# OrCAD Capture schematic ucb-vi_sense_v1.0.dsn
size C; title: UCB_VI_Sense; rev: 1.0; company: University of Arkansas (NCREPT); note: 700 W. Research Center Blvd.; note: Fayetteville, AR 72701
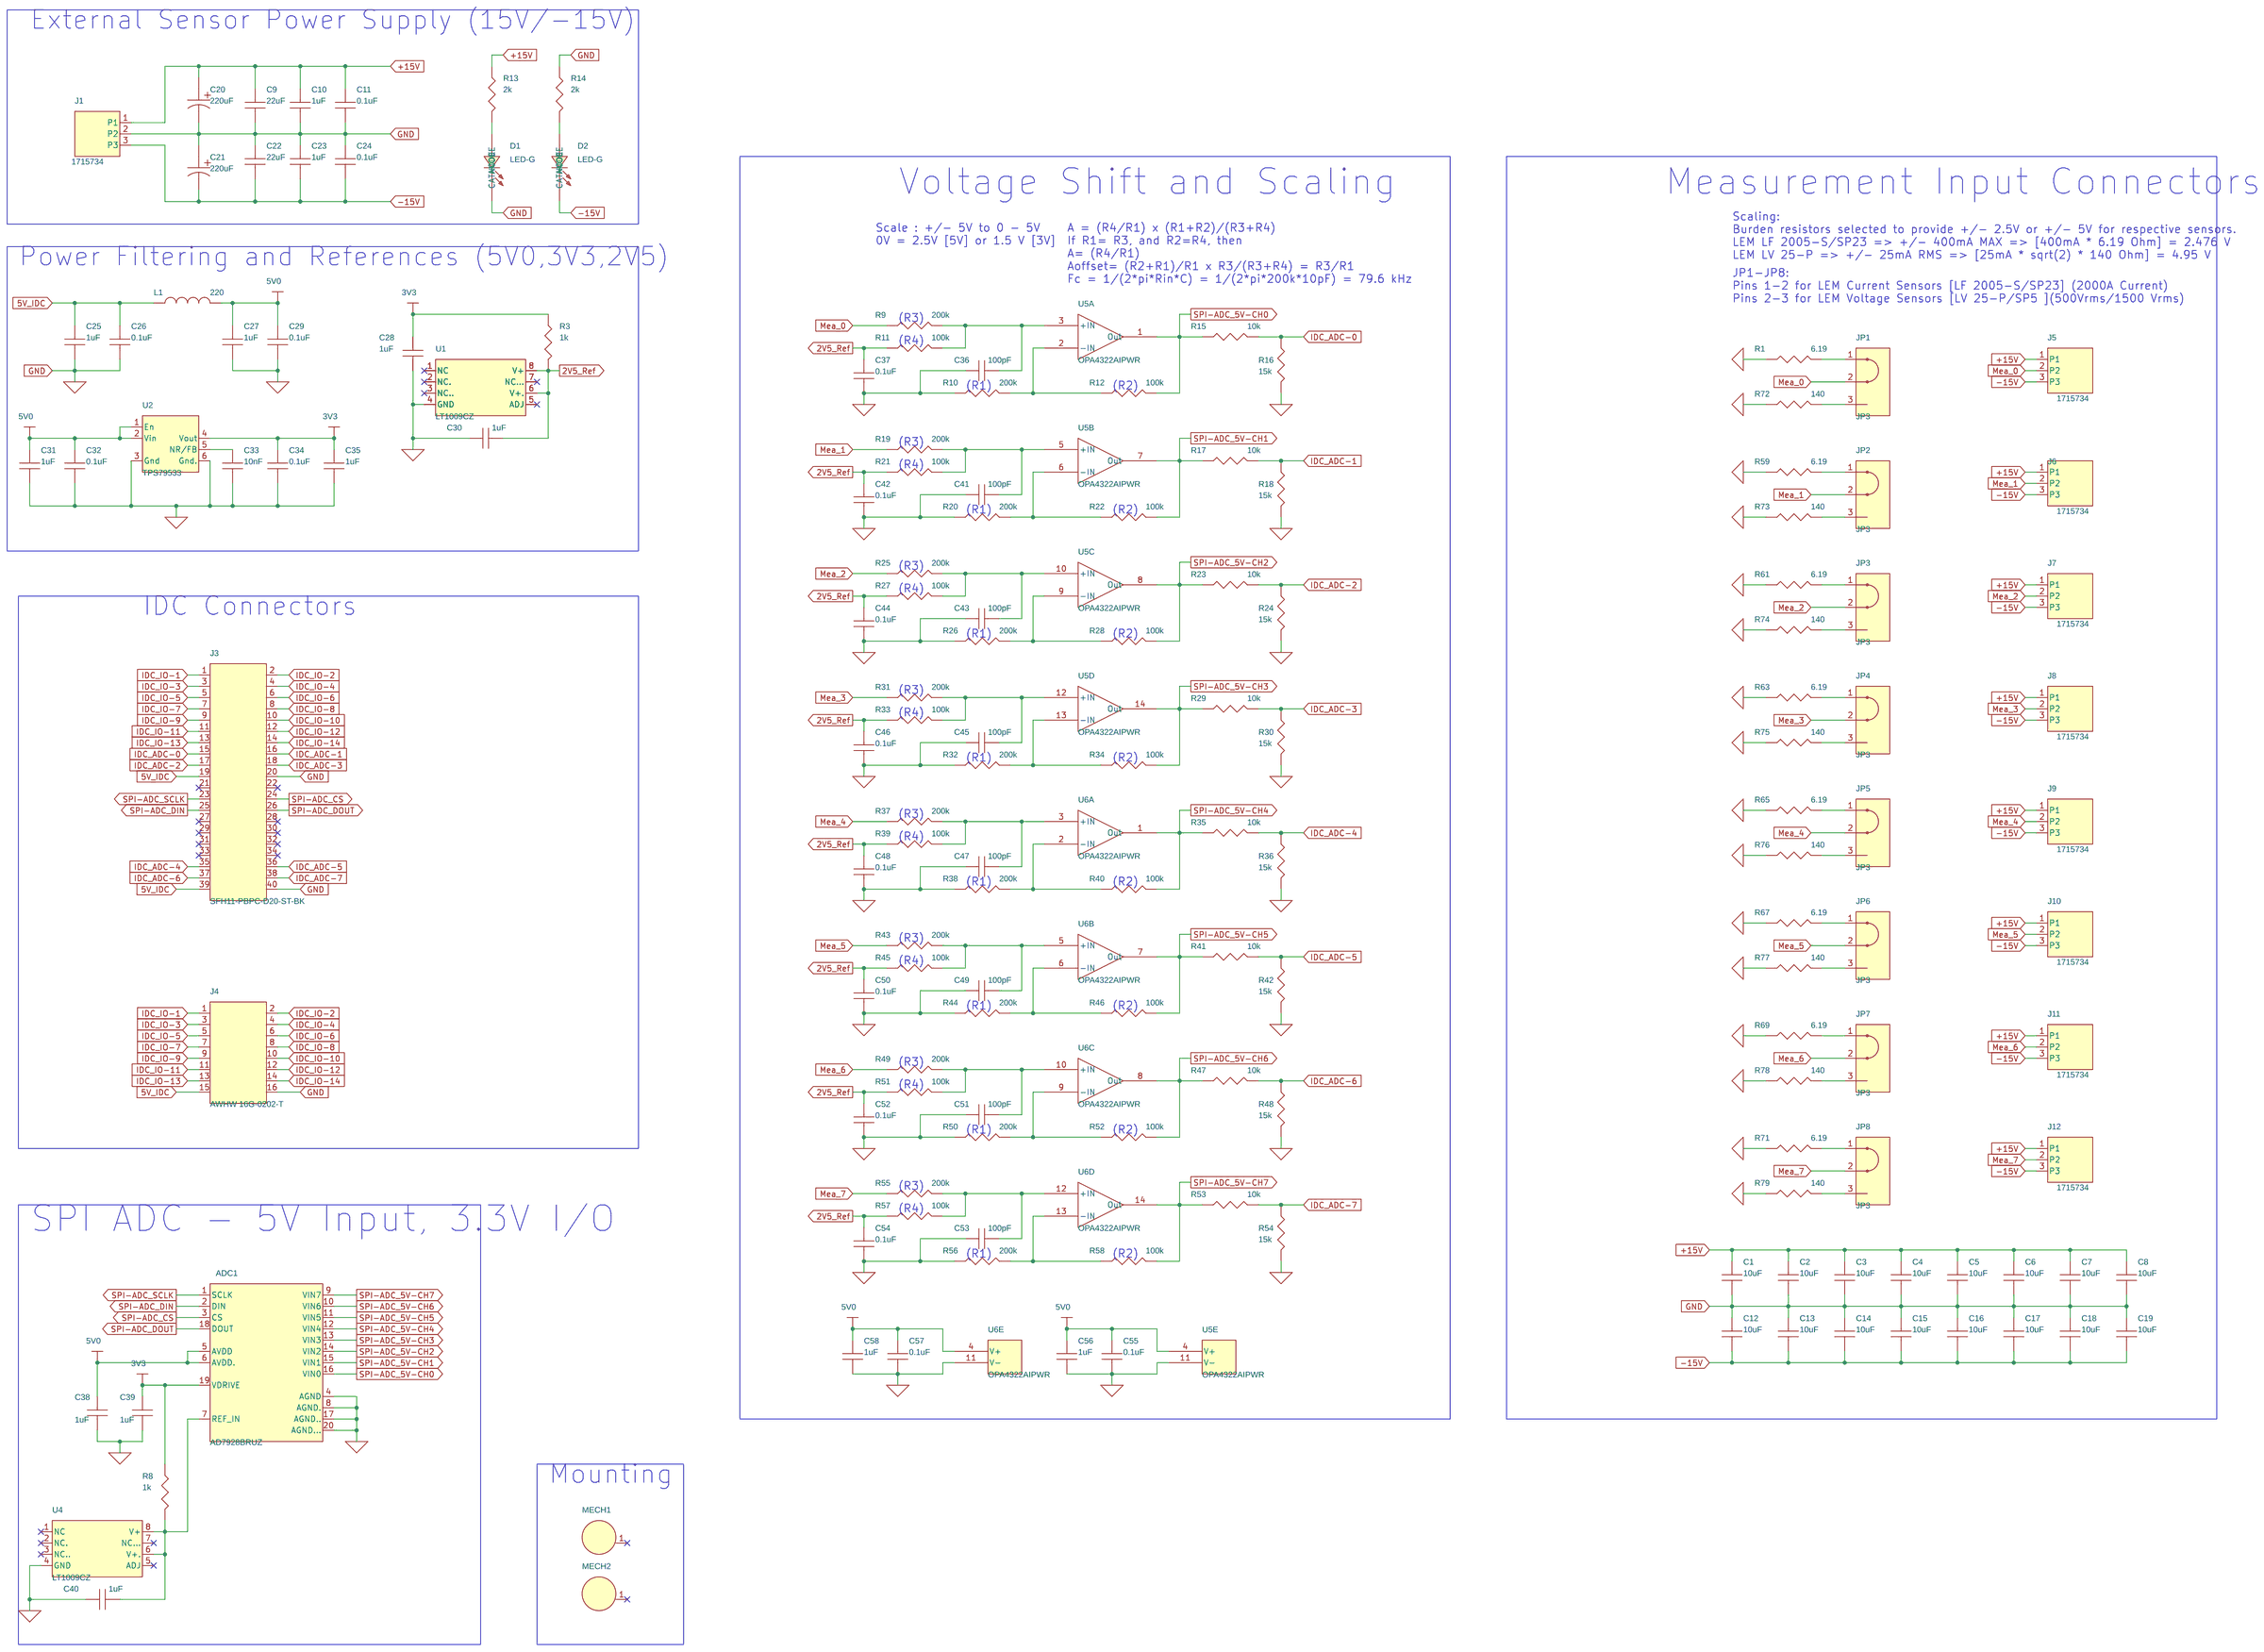
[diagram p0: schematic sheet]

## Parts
ADC1  AD7928BRUZ  [20-TSSOP]
C1  10uF  [C_1206]
C2  10uF  [C_1206]
C3  10uF  [C_1206]
C4  10uF  [C_1206]
C5  10uF  [C_1206]
C6  10uF  [C_1206]
C7  10uF  [C_1206]
C8  10uF  [C_1206]
C9  22uF  [C_0805]
C10  1uF  [C_0603]
C11  0.1uF  [C_0603]
C12  10uF  [C_1206]
C13  10uF  [C_1206]
C14  10uF  [C_1206]
C15  10uF  [C_1206]
C16  10uF  [C_1206]
C17  10uF  [C_1206]
C18  10uF  [C_1206]
C19  10uF  [C_1206]
C20  220uF  [EEE-FK-F]
C21  220uF  [EEE-FK-F]
C22  22uF  [C_0805]
C23  1uF  [C_0603]
C24  0.1uF  [C_0603]
C25  1uF  [C_0603]
C26  0.1uF  [C_0603]
C27  1uF  [C_0603]
C28  1uF  [C_0603]
C29  0.1uF  [C_0603]
C30  1uF  [C_0603]
C31  1uF  [C_0603]
C32  0.1uF  [C_0603]
C33  10nF  [C_0603]
C34  0.1uF  [C_0603]
C35  1uF  [C_0603]
C36  100pF  [C_0603]
C37  0.1uF  [C_0603]
C38  1uF  [C_0603]
C39  1uF  [C_0603]
C40  1uF  [C_0603]
C41  100pF  [C_0603]
C42  0.1uF  [C_0603]
C43  100pF  [C_0603]
C44  0.1uF  [C_0603]
C45  100pF  [C_0603]
C46  0.1uF  [C_0603]
C47  100pF  [C_0603]
C48  0.1uF  [C_0603]
C49  100pF  [C_0603]
C50  0.1uF  [C_0603]
C51  100pF  [C_0603]
C52  0.1uF  [C_0603]
C53  100pF  [C_0603]
C54  0.1uF  [C_0603]
C55  0.1uF  [C_0603]
C56  1uF  [C_0603]
C57  0.1uF  [C_0603]
C58  1uF  [C_0603]
D1  LED-G  [LED_0805-GREEN]
D2  LED-G  [LED_0805-GREEN]
J1  1715734  [1715734]
J3  SFH11-PBPC-D20-ST-BK  [40-IDC-F_MNT]
J4  AWHW 16G-0202-T  [16-IDC-M]
J5  1715734  [1715734]
J6  1715734  [1715734]
J7  1715734  [1715734]
J8  1715734  [1715734]
J9  1715734  [1715734]
J10  1715734  [1715734]
J11  1715734  [1715734]
J12  1715734  [1715734]
JP1  JP3  [J_1X3]
JP2  JP3  [J_1X3]
JP3  JP3  [J_1X3]
JP4  JP3  [J_1X3]
JP5  JP3  [J_1X3]
JP6  JP3  [J_1X3]
JP7  JP3  [J_1X3]
JP8  JP3  [J_1X3]
L1  220  [L_0805]
MECH1  Mech_Hole  [4-40_SCREW]
MECH2  Mech_Hole  [4-40_SCREW]
R1  6.19  [R_2512]
R3  1k  [R_0805]
R8  1k  [R_0805]
R9  200k  [R_0603]
R10  200k  [R_0603]
R11  100k  [R_0603]
R12  100k  [R_0603]
R13  2k  [R_0603]
R14  2k  [R_0603]
R15  10k  [R_0603]
R16  15k  [R_0603]
R17  10k  [R_0603]
R18  15k  [R_0603]
R19  200k  [R_0603]
R20  200k  [R_0603]
R21  100k  [R_0603]
R22  100k  [R_0603]
R23  10k  [R_0603]
R24  15k  [R_0603]
R25  200k  [R_0603]
R26  200k  [R_0603]
R27  100k  [R_0603]
R28  100k  [R_0603]
R29  10k  [R_0603]
R30  15k  [R_0603]
R31  200k  [R_0603]
R32  200k  [R_0603]
R33  100k  [R_0603]
R34  100k  [R_0603]
R35  10k  [R_0603]
R36  15k  [R_0603]
R37  200k  [R_0603]
R38  200k  [R_0603]
R39  100k  [R_0603]
R40  100k  [R_0603]
R41  10k  [R_0603]
R42  15k  [R_0603]
R43  200k  [R_0603]
R44  200k  [R_0603]
R45  100k  [R_0603]
R46  100k  [R_0603]
R47  10k  [R_0603]
R48  15k  [R_0603]
R49  200k  [R_0603]
R50  200k  [R_0603]
R51  100k  [R_0603]
R52  100k  [R_0603]
R53  10k  [R_0603]
R54  15k  [R_0603]
R55  200k  [R_0603]
R56  200k  [R_0603]
R57  100k  [R_0603]
R58  100k  [R_0603]
R59  6.19  [R_2512]
R61  6.19  [R_2512]
R63  6.19  [R_2512]
R65  6.19  [R_2512]
R67  6.19  [R_2512]
R69  6.19  [R_2512]
R71  6.19  [R_2512]
R72  140  [R_0805]
R73  140  [R_0805]
R74  140  [R_0805]
R75  140  [R_0805]
R76  140  [R_0805]
R77  140  [R_0805]
R78  140  [R_0805]
R79  140  [R_0805]
U1  LT1009CZ  [8-MSOP]
U2  TPS79533  [SOT-223-6]
U4  LT1009CZ  [8-MSOP]
U5  OPA4322AIPWR  [OPA4332_14-TSSOP]  (sections A,B,C,D,E)
U6  OPA4322AIPWR  [OPA4332_14-TSSOP]  (sections A,B,C,D,E)

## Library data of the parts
ADC1 = AD7928BRUZ: ADC 8-Ch, 12-Bit, 1MSPS; Manufacturer: Analog Devices; Part_Number: IC-00023; STEP_Model: TSSOP65P640X120-20N.stp; Datasheet: AnalogDevices-AD7908_7918_7928-877555.pdf
C1-C8 C12-C19 = CAP_NP: 10µF ±20% 35V X7R MLCC; Manufacturer: TDK; Manufacturer_Part_Number: C3216X7R1V106M160AC; Part_Number: Cap-00002; Tolerance: 20%; Voltage: 35V; Datasheet: TDK-mlcc_commercial_general_en.pdf
C9 C22 = CAP_NP: 22µF ±20% 25V X5R MLCC; Manufacturer: TDK; Manufacturer_Part_Number: C2012X5R1E226M125AC; Part_Number: Cap-00022; Tolerance: 20%; Voltage: 25V; Datasheet: TDK-mlcc_commercial_general_en.pdf
C10 C23 C25 C27 C28 C30 C31 C35 C38-C40 C56 C58 = CAP_NP: 1µF ±10% 35V X7R MLCC; Manufacturer: TDK; Manufacturer_Part_Number: C1608X7R1V105K080AC; Part_Number: Cap-00008; Tolerance: 10%; Voltage: 35V; Datasheet: TDK-mlcc_commercial_general_en.pdf
C11 C24 C26 C29 C32 C34 C37 C42 C44 C46 C48 C50 C52 C54 C55 C57 = CAP_NP: 0.1µF ±10% 50V X7R MLCC; Manufacturer: TDK; Manufacturer_Part_Number: C1608X7R1H104K080AA; Part_Number: Cap-00001; Tolerance: 10%; Voltage: 50V; Datasheet: TDK-mlcc_commercial_general_en.pdf
C20 C21 = CAP_P: 220µF ±20% 35V Electrolytic; Manufacturer: Panasonic; Manufacturer_Part_Number: EEE-FK1V221P; Part_Number: Cap-00024; Tolerance: 20%; Voltage: 35V; Datasheet: Panasonic-ABA0000C1181-947564.pdf
C33 = CAP_NP: 10nF ±10% 100V X7R MLCC; Manufacturer: TDK; Manufacturer_Part_Number: C1608X7R2A103K080AA; Part_Number: TMP-222; Tolerance: 10%; Voltage: 100V; Datasheet: TDK-mlcc_commercial_general_en.pdf
C36 C41 C43 C45 C47 C49 C51 C53 = CAP_NP: 100pF ±10% 100V C0G MLCC; Manufacturer: TDK; Manufacturer_Part_Number: C1608C0G2A101K080AA; Part_Number: Cap-00013; Tolerance: 10%; Voltage: 100V; Datasheet: TDK-mlcc_commercial_general_en.pdf
D1 D2 = LED: LED, 0805, Green, VF= 2.2V; Manufacturer: OSRAM; Manufacturer_Part_Number: LG R971-KN-1; Part_Number: D-00008; STEP_Model: LED_0805-Green.stp; Datasheet: OSRAM-LGR971-CHIPLED-0805-318376.pdf
J1 J5-J12 = Connector-3: PCB Terminal Block, 3-position, 90 degrees, 5.08mm; Manufacturer: Phoenix Contact; Part_Number: Con-00007; Rating: 17.5A; STEP_Model: 1715734.stp; Voltage: 400V; Datasheet: PhoenixContact-1715734.pdf
J3 = Header_2x20: 40-POS Header, Shrouded, 0.100", TH, Female w/ Mounting; Manufacturer: Sullins; Part_Number: Con-00020; STEP_Model: SFH11-P_ _C-D20-ST-_ _.stp; Datasheet: Sullins-146_PAGE119_.100_SFH11_SERIES_FEMALE_HDR_ST_RA.pdf
J4 = Header_2x8: 16-POS Header, Shrouded, 0.100", TH; Manufacturer: Assmann; Part_Number: Con-00014; STEP_Model: HDB-16.stp; User_Field1: SBH11-PBPC-D08-ST-BK; Datasheet: SBH11-PBPC-D08-ST-BK
JP1-JP8 = JP3: Male, TH, Straight, 3-Pos, 0.1" Pitch; Manufacturer: Various; Manufacturer_Part_Number: PRT-00116; Part_Number: JP-00002
L1 = Ind: Ferrite Bead, 220 Ohm @ 100 MHz, 2A; Manufacturer: Murata; Manufacturer_Part_Number: BLM21PG221SN1D; Part_Number: Ind-00001; Rating: 2A; Tolerance: 25%; Datasheet: Murata-L0110S0100BLM21P.pdf
MECH1 MECH2 = Mech_Hole: Mounting Hole for 4-40 Screw, 0.125"; Part_Number: Con-00005
R1 R59 R61 R63 R65 R67 R69 R71 = R-Standard: 6.19 Ohm, 1%, 2512; Manufacturer: KOA Speer; Manufacturer_Part_Number: RK73H3ATTE6R19F; Part_Number: TMP-230; Rating: 1W; Tolerance: 1%; Datasheet: KOA-RK73H-5715.pdf
R3 R8 = R-Standard: 1k Ohm, 1%, 0805; Manufacturer: KOA Speer; Manufacturer_Part_Number: RK73H2ATTD1001F; Part_Number: Res-00012; Rating: 0.125W; Tolerance: 1%; Datasheet: KOA-RK73H-5715.pdf
R9 R10 R19 R20 R25 R26 R31 R32 R37 R38 R43 R44 R49 R50 R55 R56 = R-Standard: 200k Ohm, 1%, 0603; Manufacturer: KOA Speer; Manufacturer_Part_Number: RK73H1JTTDD2003F; Part_Number: TMP-221; Rating: 0.1W; Tolerance: 1%; Datasheet: KOA-RK73H-5715.pdf
R11 R12 R21 R22 R27 R28 R33 R34 R39 R40 R45 R46 R51 R52 R57 R58 = R-Standard: 100k Ohm, 1%, 0603; Manufacturer: KOA Speer; Manufacturer_Part_Number: RK73H1JTTD1003F; Part_Number: TMP-220; Rating: 0.1W; Tolerance: 1%; Datasheet: KOA-RK73H-5715.pdf
R13 R14 = R-Standard: 2k Ohm, 1%, 0603; Manufacturer: KOA Speer; Manufacturer_Part_Number: RK73H1JTTD2001F; Part_Number: Res-00004; Rating: 0.1W; Tolerance: 1%; Datasheet: KOA-RK73H-5715.pdf
R15 R17 R23 R29 R35 R41 R47 R53 = R-Standard: 10k Ohm, 1%, 0603; Manufacturer: KOA Speer; Manufacturer_Part_Number: RK73H1JTTD1002F; Part_Number: Res-00031; Rating: 0.1W; Tolerance: 1%; Datasheet: KOA-RK73H-5715.pdf
R16 R18 R24 R30 R36 R42 R48 R54 = R-Standard: 15k Ohm, 1%, 0603; Manufacturer: KOA Speer; Manufacturer_Part_Number: RK73H1JTTD1502F; Part_Number: Res-00037; Rating: 0.1W; Tolerance: 1%; Datasheet: KOA-RK73H-5715.pdf
R72-R79 = R-Standard: 140 Ohm, 1%, 0805; Manufacturer: KOA Speer; Manufacturer_Part_Number: RK73H2ATTD1400F; Part_Number: TMP-239; Rating: 0.25W; Tolerance: 1%; Datasheet: KOA-RK73H-5715.pdf
U1 U4 = LT1009CZ: 2.5V Voltage Reference, ±0.2%, SMD; Manufacturer: Linear Tech; Manufacturer_Part_Number: LT1009CMS8#PBF; Part_Number: IC-00024; STEP_Model: MSOP8.stp; Datasheet: LinearTech-1009ff.pdf
U2 = TPS795: LDO Voltage Reg, 3.3V, 500mA, 2%; Manufacturer: TI; Manufacturer_Part_Number: TPS79533DCQR; Part_Number: IC-00025; STEP_Model: SOT-223-6.stp; Datasheet: TI-tps795-706600.pdf
U5 U6 = OPA4322AIPWR: Quad OpAmp, 20 MHz; Manufacturer: TI; Part_Number: IC-00012; STEP_Model: TSSOP14.stp; User_Field1: https://www.google.com/; Datasheet: TI-opa4322.pdf

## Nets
2V5_Ref: C30.2 C37.1 C42.1 C44.1 C46.1 C48.1 C50.1 C52.1 C54.1 R3.2 R11.1 R21.1 R27.1 R33.1 R39.1 R45.1 R51.1 R57.1 U1.6(V+.) U1.8(V+)
3V3: ADC1.19(VDRIVE) C28.1 C34.1 C35.1 C39.1 R3.1 R8.1 U2.4(Vout)
5V0: ADC1.5(AVDD) ADC1.6(AVDD.) C27.1 C29.1 C31.1 C32.1 C38.1 C55.1 C56.1 C57.1 C58.1 L1.2 U2.1(En) U2.2(Vin) U5.4(V+) U6.4(V+)
5V_IDC: C25.1 C26.1 J3.19 J3.39 J4.15 L1.1
+15V: C1.1 C2.1 C3.1 C4.1 C5.1 C6.1 C7.1 C8.1 C9.1 C10.1 C11.1 C20.1 J1.1(P1) J5.1(P1) J6.1(P1) J7.1(P1) J8.1(P1) J9.1(P1) J10.1(P1) J11.1(P1) J12.1(P1) R13.1
-15V: C12.2 C13.2 C14.2 C15.2 C16.2 C17.2 C18.2 C19.2 C21.2 C22.2 C23.2 C24.2 D2.1(CATHODE) J1.3(P3) J5.3(P3) J6.3(P3) J7.3(P3) J8.3(P3) J9.3(P3) J10.3(P3) J11.3(P3) J12.3(P3)
GND_SIGNAL: ADC1.4(AGND) ADC1.8(AGND.) ADC1.17(AGND..) ADC1.20(AGND...) C1.2 C2.2 C3.2 C4.2 C5.2 C6.2 C7.2 C8.2 C9.2 C10.2 C11.2 C12.1 C13.1 C14.1 C15.1 C16.1 C17.1 C18.1 C19.1 C20.2 C21.1 C22.1 C23.1 C24.1 C25.2 C26.2 C27.2 C28.2 C29.2 C30.1 C31.2 C32.2 C33.2 C34.2 C35.2 C36.1 C37.2 C38.2 C39.2 C40.1 C41.1 C42.2 C43.1 C44.2 C45.1 C46.2 C47.1 C48.2 C49.1 C50.2 C51.1 C52.2 C53.1 C54.2 C55.2 C56.2 C57.2 C58.2 D1.1(CATHODE) J1.2(P2) J3.20 J3.40 J4.16 R1.1 R10.1 R14.1 R16.2 R18.2 R20.1 R24.2 R26.1 R30.2 R32.1 R36.2 R38.1 R42.2 R44.1 R48.2 R50.1 R54.2 R56.1 R59.1 R61.1 R63.1 R65.1 R67.1 R69.1 R71.1 R72.1 R73.1 R74.1 R75.1 R76.1 R77.1 R78.1 R79.1 U1.4(GND) U2.3(Gnd) U2.6(Gnd.) U4.4(GND) U5.11(V-) U6.11(V-)
IDC_ADC-0: J3.15 R15.2 R16.1
IDC_ADC-1: J3.16 R17.2 R18.1
IDC_ADC-2: J3.17 R23.2 R24.1
IDC_ADC-3: J3.18 R29.2 R30.1
IDC_ADC-4: J3.35 R35.2 R36.1
IDC_ADC-5: J3.36 R41.2 R42.1
IDC_ADC-6: J3.37 R47.2 R48.1
IDC_ADC-7: J3.38 R53.2 R54.1
IDC_IO-1: J3.1 J4.1
IDC_IO-2: J3.2 J4.2
IDC_IO-3: J3.3 J4.3
IDC_IO-4: J3.4 J4.4
IDC_IO-5: J3.5 J4.5
IDC_IO-6: J3.6 J4.6
IDC_IO-7: J3.7 J4.7
IDC_IO-8: J3.8 J4.8
IDC_IO-9: J3.9 J4.9
IDC_IO-10: J3.10 J4.10
IDC_IO-11: J3.11 J4.11
IDC_IO-12: J3.12 J4.12
IDC_IO-13: J3.13 J4.13
IDC_IO-14: J3.14 J4.14
Mea_0: J5.2(P2) JP1.2 R9.1
Mea_1: J6.2(P2) JP2.2 R19.1
Mea_2: J7.2(P2) JP3.2 R25.1
Mea_3: J8.2(P2) JP4.2 R31.1
Mea_4: J9.2(P2) JP5.2 R37.1
Mea_5: J10.2(P2) JP6.2 R43.1
Mea_6: J11.2(P2) JP7.2 R49.1
Mea_7: J12.2(P2) JP8.2 R55.1
SPI-ADC_5V-CH0: ADC1.16(VIN0) R12.2 R15.1 U5.1(Out)
SPI-ADC_5V-CH1: ADC1.15(VIN1) R17.1 R22.2 U5.7(Out)
SPI-ADC_5V-CH2: ADC1.14(VIN2) R23.1 R28.2 U5.8(Out)
SPI-ADC_5V-CH3: ADC1.13(VIN3) R29.1 R34.2 U5.14(Out)
SPI-ADC_5V-CH4: ADC1.12(VIN4) R35.1 R40.2 U6.1(Out)
SPI-ADC_5V-CH5: ADC1.11(VIN5) R41.1 R46.2 U6.7(Out)
SPI-ADC_5V-CH6: ADC1.10(VIN6) R47.1 R52.2 U6.8(Out)
SPI-ADC_5V-CH7: ADC1.9(VIN7) R53.1 R58.2 U6.14(Out)
SPI-ADC_CS: ADC1.3(CS) J3.24
SPI-ADC_DIN: ADC1.2(DIN) J3.25
SPI-ADC_DOUT: ADC1.18(DOUT) J3.26
SPI-ADC_SCLK: ADC1.1(SCLK) J3.23
N365232: ADC1.7(REF_IN) C40.2 R8.2 U4.6(V+.) U4.8(V+)
N367140: C36.2 R9.2 R11.2 U5.3(+IN)
N367168: R10.2 R12.1 U5.2(-IN)
N370101: C33.1 U2.5(NR/FB)
N387715: JP1.1 R1.2
N388314: JP1.3 R72.2
N392987: D2.2(ANODE) R14.2
N392991: D1.2(ANODE) R13.2
N402358: C41.2 R19.2 R21.2 U5.5(+IN)
N402362: R20.2 R22.1 U5.6(-IN)
N403154: C43.2 R25.2 R27.2 U5.10(+IN)
N403158: R26.2 R28.1 U5.9(-IN)
N403978: C45.2 R31.2 R33.2 U5.12(+IN)
N403982: R32.2 R34.1 U5.13(-IN)
N404826: C47.2 R37.2 R39.2 U6.3(+IN)
N404830: R38.2 R40.1 U6.2(-IN)
N405710: C49.2 R43.2 R45.2 U6.5(+IN)
N405714: R44.2 R46.1 U6.6(-IN)
N406610: C51.2 R49.2 R51.2 U6.10(+IN)
N406614: R50.2 R52.1 U6.9(-IN)
N407827: C53.2 R55.2 R57.2 U6.12(+IN)
N407831: R56.2 R58.1 U6.13(-IN)
N416291: JP2.1 R59.2
N416303: JP2.3 R73.2
N416911: JP3.1 R61.2
N416923: JP3.3 R74.2
N417886: JP4.1 R63.2
N417898: JP4.3 R75.2
N420263: JP5.1 R65.2
N420287: JP5.3 R76.2
N420898: JP6.1 R67.2
N420922: JP6.3 R77.2
N421540: JP7.1 R69.2
N421564: JP7.3 R78.2
N422187: JP8.1 R71.2
N422211: JP8.3 R79.2

Not connected (* = marked no-connect by the designer): J3 21* 22* 27* 28* 29* 30* 31* 32* 33* 34*; MECH1 1*; MECH2 1*; U1 1(NC)* 2(NC.)* 3(NC..)* 5(ADJ)* 7(NC...)*; U4 1(NC)* 2(NC.)* 3(NC..)* 5(ADJ)* 7(NC...)*

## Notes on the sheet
- External Sensor Power Supply (15V/-15V)
- Voltage Shift and Scaling
- Measurement Input Connectors
- Scaling:
  Burden resistors selected to provide +/- 2.5V or +/- 5V for respective sensors.
  LEM LF 2005-S/SP23 => +/- 400mA MAX => [400mA * 6.19 Ohm] = 2.476 V
  LEM LV 25-P => +/- 25mA RMS => [25mA * sqrt(2) * 140 Ohm] = 4.95 V
- Scale : +/- 5V to 0 - 5V
  0V = 2.5V [5V] or 1.5 V [3V]
- A = (R4/R1) x (R1+R2)/(R3+R4)
  If R1= R3, and R2=R4, then
  A= (R4/R1)
  Aoffset= (R2+R1)/R1 x R3/(R3+R4) = R3/R1
  Fc = 1/(2*pi*Rin*C) = 1/(2*pi*200k*10pF) = 79.6 kHz
- Power Filtering and References (5V0,3V3,2V5)
- JP1-JP8:
  Pins 1-2 for LEM Current Sensors [LF 2005-S/SP23] (2000A Current)
  Pins 2-3 for LEM Voltage Sensors [LV 25-P/SP5 ](500Vrms/1500 Vrms)
- (R3)
- (R4)
- (R1)
- (R2)
- (R3)
- (R4)
- (R1)
- (R2)
- (R3)
- (R4)
- IDC Connectors
- (R1)
- (R2)
- (R3)
- (R4)
- (R1)
- (R2)
- (R3)
- (R4)
- (R1)
- (R2)
- (R3)
- (R4)
- (R1)
- (R2)
- (R3)
- (R4)
- (R1)
- (R2)
- (R3)
- SPI ADC - 5V Input, 3.3V I/O
- (R4)
- (R1)
- (R2)
- Mounting
